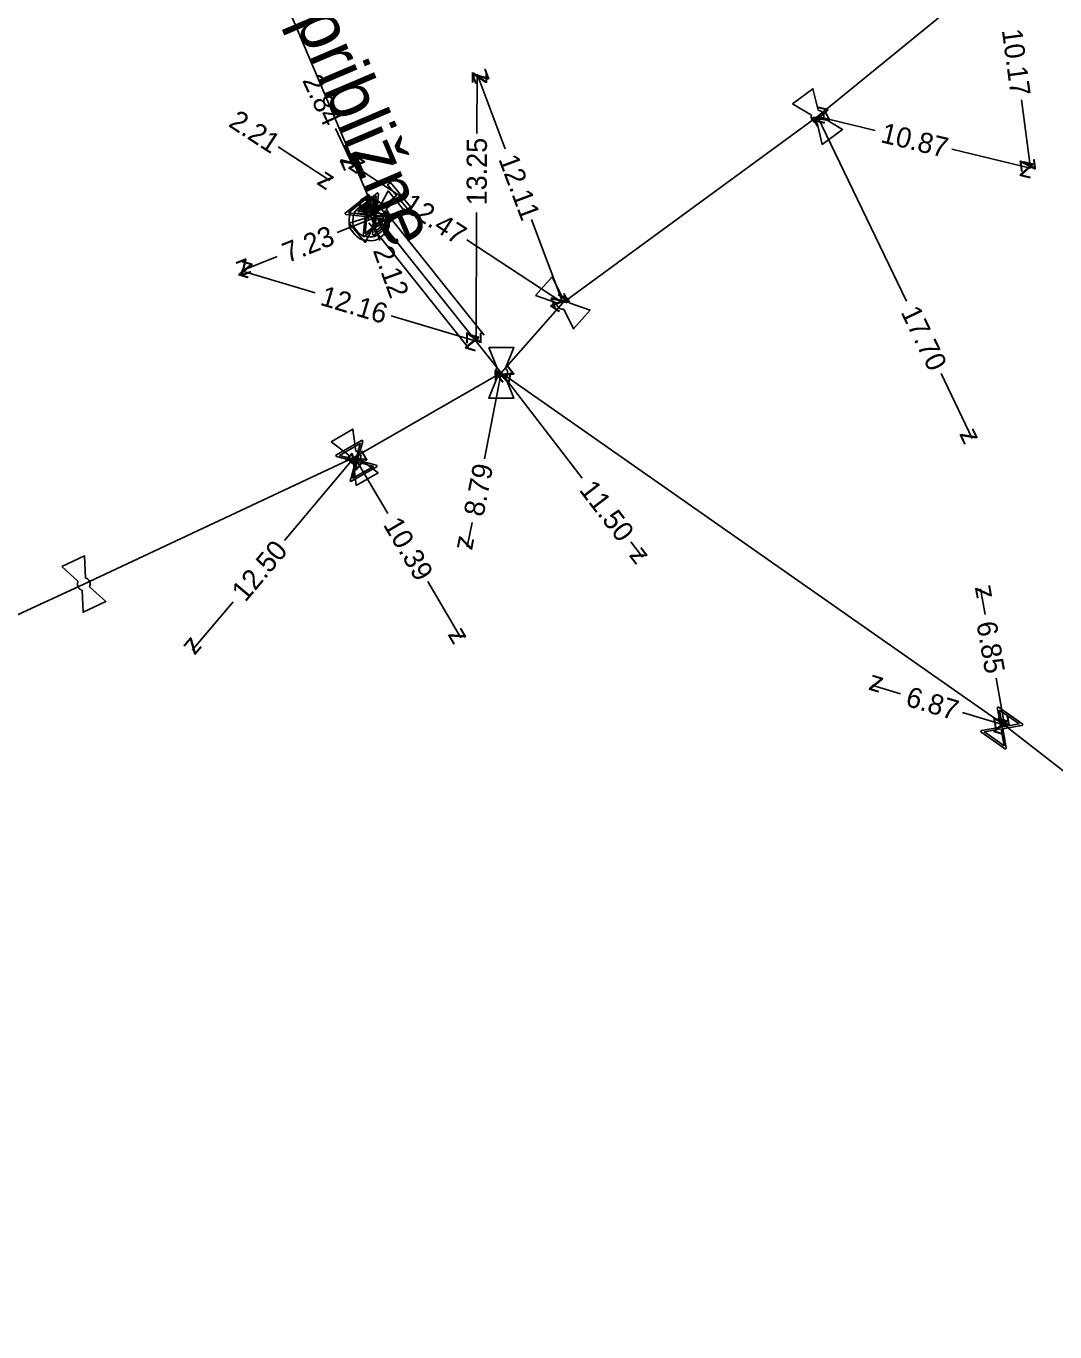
# Model space of a CAD drawing. Extents: x -638315 to -636370, y -1116147 to -1115110.
# Drawn here: x -637261.5 to -637210.5, y -1115972.2 to -1115907.4 of the extents above; entities that cross this region are included whole.
import ezdxf

# ---------------------------------------------------------------- set-up
doc = ezdxf.new("R2010")
doc.units = 0
for name, color, linetype in [('Default', 7, 'Continuous'), ('VP Chránička', 7, 'Continuous'), ('VP Hydrant', 7, 'Continuous'), ('VP Kótování', 7, 'Continuous'), ('VP Lomový bod', 7, 'Continuous'), ('VP Popis nerozlišený', 7, 'Continuous'), ('VP Přípojka', 7, 'Continuous'), ('VP Řad', 7, 'Continuous'), ('VP Šoupě', 7, 'Continuous')]:
    doc.layers.add(name, color=color, linetype=linetype)

msp = doc.modelspace()

# ---------------------------------------------------------------- linework, layer by layer
at = {"layer": 'Default'}
for points in [[(-637222.235, -1115911.617), (-637222.183, -1115911.622), (-637222.134, -1115911.643), (-637222.056, -1115911.68), (-637222.008, -1115911.746), (-637221.96, -1115911.812), (-637221.95, -1115911.896), (-637221.944, -1115911.95), (-637221.956, -1115912.001)], [(-637222.285, -1115912.242), (-637222.338, -1115912.238), (-637222.388, -1115912.215), (-637222.464, -1115912.181), (-637222.513, -1115912.115), (-637222.561, -1115912.049), (-637222.571, -1115911.962), (-637222.578, -1115911.91), (-637222.565, -1115911.858)], [(-637243.654, -1115916.505), (-637243.448, -1115916.801), (-637243.483, -1115917.165), (-637243.523, -1115917.576), (-637243.844, -1115917.841), (-637244.163, -1115918.105), (-637244.575, -1115918.066), (-637244.986, -1115918.026), (-637245.252, -1115917.706), (-637245.514, -1115917.388), (-637245.476, -1115916.976), (-637245.438, -1115916.564), (-637245.119, -1115916.3), (-637244.799, -1115916.035), (-637244.387, -1115916.073), (-637244.021, -1115916.104), (-637243.771, -1115916.364)], [(-637244.975, -1115916.31), (-637244.975, -1115916.216), (-637244.927, -1115916.126), (-637244.878, -1115916.036), (-637244.788, -1115915.986), (-637244.698, -1115915.935), (-637244.6, -1115915.935), (-637244.502, -1115915.935), (-637244.413, -1115915.984), (-637244.324, -1115916.034), (-637244.274, -1115916.123), (-637244.225, -1115916.213), (-637244.225, -1115916.31), (-637244.225, -1115916.407), (-637244.274, -1115916.497), (-637244.324, -1115916.586), (-637244.413, -1115916.636), (-637244.502, -1115916.685), (-637244.6, -1115916.685), (-637244.698, -1115916.685), (-637244.788, -1115916.635), (-637244.878, -1115916.584), (-637244.927, -1115916.495), (-637244.975, -1115916.405), (-637244.975, -1115916.31)], [(-637244.928, -1115916.31), (-637244.928, -1115916.393), (-637244.886, -1115916.472), (-637244.844, -1115916.55), (-637244.765, -1115916.594), (-637244.686, -1115916.638), (-637244.6, -1115916.638), (-637244.514, -1115916.638), (-637244.436, -1115916.595), (-637244.359, -1115916.552), (-637244.315, -1115916.474), (-637244.272, -1115916.395), (-637244.272, -1115916.31), (-637244.272, -1115916.225), (-637244.315, -1115916.146), (-637244.359, -1115916.068), (-637244.436, -1115916.025), (-637244.514, -1115915.982), (-637244.6, -1115915.982), (-637244.686, -1115915.982), (-637244.765, -1115916.026), (-637244.844, -1115916.071), (-637244.886, -1115916.149), (-637244.928, -1115916.228), (-637244.928, -1115916.31)], [(-637243.854, -1115916.549), (-637244.069, -1115916.289), (-637244.403, -1115916.257), (-637244.737, -1115916.225), (-637244.998, -1115916.441), (-637245.258, -1115916.656), (-637245.29, -1115916.99), (-637245.321, -1115917.325), (-637245.106, -1115917.585), (-637244.892, -1115917.844), (-637244.557, -1115917.876), (-637244.222, -1115917.908), (-637243.962, -1115917.693), (-637243.701, -1115917.477), (-637243.67, -1115917.143), (-637243.638, -1115916.809), (-637243.854, -1115916.549)], [(-637244.432, -1115916.884), (-637244.432, -1115916.831), (-637244.412, -1115916.78), (-637244.382, -1115916.701), (-637244.319, -1115916.649), (-637244.256, -1115916.597), (-637244.171, -1115916.582), (-637244.119, -1115916.572), (-637244.067, -1115916.581)], [(-637243.806, -1115916.896), (-637243.807, -1115916.948), (-637243.826, -1115916.998), (-637243.858, -1115917.079), (-637243.921, -1115917.131), (-637243.984, -1115917.183), (-637244.067, -1115917.198), (-637244.121, -1115917.207), (-637244.173, -1115917.198)], [(-637234.846, -1115921.469), (-637234.899, -1115921.477), (-637234.952, -1115921.466), (-637235.035, -1115921.449), (-637235.096, -1115921.395), (-637235.157, -1115921.341), (-637235.186, -1115921.259), (-637235.204, -1115921.209), (-637235.203, -1115921.156)], [(-637234.933, -1115920.849), (-637234.882, -1115920.842), (-637234.829, -1115920.852), (-637234.745, -1115920.871), (-637234.683, -1115920.925), (-637234.622, -1115920.979), (-637234.594, -1115921.059), (-637234.576, -1115921.11), (-637234.577, -1115921.163)], [(-637238.144, -1115924.867), (-637238.184, -1115924.833), (-637238.211, -1115924.785), (-637238.253, -1115924.712), (-637238.253, -1115924.63), (-637238.253, -1115924.548), (-637238.21, -1115924.473), (-637238.184, -1115924.426), (-637238.144, -1115924.392)], [(-637237.735, -1115924.392), (-637237.696, -1115924.426), (-637237.669, -1115924.473), (-637237.628, -1115924.548), (-637237.628, -1115924.63), (-637237.628, -1115924.712), (-637237.669, -1115924.785), (-637237.696, -1115924.833), (-637237.736, -1115924.867)], [(-637245.271, -1115929.12), (-637245.323, -1115929.111), (-637245.37, -1115929.083), (-637245.443, -1115929.04), (-637245.484, -1115928.969), (-637245.524, -1115928.898), (-637245.525, -1115928.811), (-637245.526, -1115928.758), (-637245.508, -1115928.709)], [(-637245.154, -1115928.505), (-637245.103, -1115928.515), (-637245.056, -1115928.542), (-637244.983, -1115928.587), (-637244.942, -1115928.657), (-637244.901, -1115928.728), (-637244.9, -1115928.813), (-637244.9, -1115928.867), (-637244.918, -1115928.917)], [(-637258.555, -1115934.797), (-637258.505, -1115934.812), (-637258.461, -1115934.842), (-637258.392, -1115934.893), (-637258.357, -1115934.967), (-637258.322, -1115935.041), (-637258.329, -1115935.125), (-637258.333, -1115935.18), (-637258.355, -1115935.228)], [(-637258.724, -1115935.401), (-637258.775, -1115935.387), (-637258.82, -1115935.355), (-637258.888, -1115935.306), (-637258.923, -1115935.232), (-637258.958, -1115935.158), (-637258.951, -1115935.072), (-637258.948, -1115935.019), (-637258.926, -1115934.971)]]:
    msp.add_open_spline(points, degree=3, dxfattribs=at)
at = {"layer": 'VP Chránička'}
for points in [[(-637243.729, -1115916.578), (-637238.797, -1115922.755)], [(-637244.51, -1115917.201), (-637239.578, -1115923.378)]]:
    msp.add_lwpolyline(points, dxfattribs=at)
at = {"layer": 'VP Hydrant'}
msp.add_lwpolyline([(-637243.771, -1115916.364), (-637243.139, -1115915.841), (-637243.579, -1115915.31), (-637243.437, -1115915.193), (-637242.441, -1115916.396), (-637242.583, -1115916.513), (-637243.022, -1115915.982), (-637243.654, -1115916.505)], dxfattribs=at)
at = {"layer": 'VP Kótování'}
for points in [[(-637239.151, -1115912.767), (-637239.14, -1115909.82)], [(-637237.75, -1115913.528), (-637239.14, -1115909.82)], [(-637212.158, -1115911.104), (-637211.7, -1115914.49)], [(-637219.406, -1115912.622), (-637222.26, -1115911.93)], [(-637217.859, -1115921.082), (-637222.26, -1115911.93)], [(-637246.165, -1115912.511), (-637245.32, -1115914.32)], [(-637249.004, -1115913.43), (-637246.45, -1115915.1)], [(-637245.677, -1115913.333), (-637245.32, -1115914.32)], [(-637215.607, -1115913.543), (-637211.7, -1115914.49)], [(-637242.924, -1115915.891), (-637245.32, -1115914.32)], [(-637243.966, -1115918.063), (-637244.6, -1115916.31)], [(-637243.721, -1115916.885), (-637244.6, -1115916.31)], [(-637239.165, -1115916.677), (-637239.188, -1115923.067)], [(-637246.072, -1115917.67), (-637244.12, -1115916.89)], [(-637243.676, -1115917.841), (-637244.12, -1115916.89)], [(-637236.44, -1115917.024), (-637234.89, -1115921.16)], [(-637239.656, -1115918.034), (-637234.89, -1115921.16)], [(-637249.052, -1115918.86), (-637250.83, -1115919.57)], [(-637247.17, -1115920.67), (-637250.83, -1115919.57)], [(-637243.395, -1115921.803), (-637239.188, -1115923.067)], [(-637238.776, -1115928.897), (-637237.94, -1115924.63)], [(-637233.934, -1115929.856), (-637237.94, -1115924.63)], [(-637216.141, -1115924.654), (-637214.59, -1115927.88)], [(-637248.687, -1115932.943), (-637245.213, -1115928.813)], [(-637243.57, -1115931.601), (-637245.213, -1115928.813)], [(-637239.392, -1115932.046), (-637239.63, -1115933.26)], [(-637231.522, -1115933.001), (-637230.94, -1115933.76)], [(-637241.586, -1115934.968), (-637239.94, -1115937.76)], [(-637213.958, -1115936.602), (-637214.18, -1115935.34)], [(-637251.238, -1115935.976), (-637253.26, -1115938.38)], [(-637218.143, -1115940.53), (-637219.57, -1115940.1)], [(-637213.401, -1115939.764), (-637212.993, -1115942.084)], [(-637215.072, -1115941.457), (-637212.993, -1115942.084)]]:
    msp.add_lwpolyline(points, dxfattribs=at)
at = {"layer": 'VP Lomový bod'}
for points in [[(-637223.502, -1115911.29), (-637222.493, -1115910.552), (-637222.235, -1115911.617)], [(-637222.565, -1115911.858), (-637223.502, -1115911.29)], [(-637221.956, -1115912.001), (-637221.018, -1115912.571), (-637222.027, -1115913.308), (-637222.285, -1115912.242)], [(-637244.067, -1115916.581), (-637243.556, -1115915.612)], [(-637243.556, -1115915.612), (-637242.759, -1115916.575), (-637243.806, -1115916.896)], [(-637244.173, -1115917.198), (-637244.685, -1115918.168), (-637245.482, -1115917.205), (-637244.432, -1115916.884)], [(-637236.241, -1115920.804), (-637235.416, -1115919.865), (-637234.933, -1115920.849)], [(-637235.203, -1115921.156), (-637236.241, -1115920.804)], [(-637234.577, -1115921.163), (-637233.538, -1115921.516), (-637234.363, -1115922.455), (-637234.846, -1115921.469)], [(-637238.565, -1115923.38), (-637237.315, -1115923.38), (-637237.735, -1115924.392)], [(-637238.144, -1115924.392), (-637238.565, -1115923.38)], [(-637237.736, -1115924.867), (-637237.315, -1115925.88), (-637238.565, -1115925.88), (-637238.144, -1115924.867)], [(-637246.378, -1115928.041), (-637245.294, -1115927.418), (-637245.154, -1115928.505)], [(-637245.508, -1115928.709), (-637246.378, -1115928.041)], [(-637244.918, -1115928.917), (-637244.048, -1115929.585), (-637245.131, -1115930.208), (-637245.271, -1115929.12)], [(-637259.736, -1115934.233), (-637258.604, -1115933.703), (-637258.555, -1115934.797)], [(-637258.926, -1115934.971), (-637259.736, -1115934.233)], [(-637258.355, -1115935.228), (-637257.544, -1115935.967), (-637258.676, -1115936.497), (-637258.724, -1115935.401)]]:
    msp.add_lwpolyline(points, dxfattribs=at)
at = {"layer": 'VP Přípojka'}
for points in [[(-637244.12, -1115916.89), (-637258.991, -1115881.881)], [(-637244.507, -1115917.006), (-637244.695, -1115916.772), (-637244.883, -1115916.538)], [(-637245.213, -1115928.813), (-637245.12, -1115928.99)], [(-637213.13, -1115942.23), (-637212.993, -1115942.084)]]:
    msp.add_lwpolyline(points, dxfattribs=at)
at = {"layer": 'VP Řad'}
for points in [[(-637237.94, -1115924.63), (-637234.89, -1115921.16), (-637222.26, -1115911.93), (-637213.062, -1115904.409), (-637210.258, -1115901.954), (-637204.83, -1115897.2), (-637199.8, -1115891.84), (-637193.2, -1115884.012), (-637190.02, -1115880.24), (-637188.874, -1115878.812), (-637184.355, -1115873.178), (-637181.977, -1115870.214), (-637180.72, -1115868.647), (-637176.92, -1115863.91)], [(-637244.6, -1115916.31), (-637244.12, -1115916.89), (-637237.94, -1115924.63)], [(-637237.94, -1115924.63), (-637245.213, -1115928.813), (-637258.64, -1115935.1), (-637264.53, -1115937.81), (-637268.28, -1115940.82), (-637282.713, -1115953.66), (-637288.782, -1115958.83), (-637300.546, -1115968.853), (-637302.282, -1115970.332)], [(-637237.94, -1115924.63), (-637212.993, -1115942.084), (-637200.588, -1115951.742), (-637198.29, -1115953.52), (-637189.11, -1115959.05), (-637187.26, -1115960.04), (-637174.427, -1115967.22), (-637166.44, -1115972.16)]]:
    msp.add_lwpolyline(points, dxfattribs=at)
at = {"layer": 'VP Šoupě'}
for points in [[(-637243.586, -1115916.953), (-637244.755, -1115917.894), (-637244.796, -1115917.842), (-637244.778, -1115917.715), (-637244.689, -1115916.88), (-637245.654, -1115916.776), (-637245.695, -1115916.725), (-637244.526, -1115915.785), (-637244.485, -1115915.836), (-637244.592, -1115916.802), (-637243.756, -1115916.891), (-637243.627, -1115916.902), (-637243.586, -1115916.953)], [(-637245.518, -1115916.703), (-637244.679, -1115916.792), (-637244.59, -1115915.956), (-637245.518, -1115916.703)], [(-637243.123, -1115916.859), (-637244.279, -1115917.816), (-637244.321, -1115917.765), (-637244.304, -1115917.637), (-637244.227, -1115916.801), (-637245.193, -1115916.711), (-637245.235, -1115916.66), (-637244.079, -1115915.704), (-637244.037, -1115915.754), (-637244.131, -1115916.722), (-637243.294, -1115916.799), (-637243.165, -1115916.808), (-637243.123, -1115916.859)], [(-637245.058, -1115916.635), (-637244.218, -1115916.713), (-637244.14, -1115915.876), (-637245.058, -1115916.635)], [(-637243.304, -1115916.887), (-637244.139, -1115916.809), (-637244.217, -1115917.643), (-637243.304, -1115916.887)], [(-637243.767, -1115916.979), (-637244.601, -1115916.889), (-637244.69, -1115917.722), (-637243.767, -1115916.979)], [(-637244.096, -1115929.266), (-637245.396, -1115930.014), (-637245.429, -1115929.957), (-637245.392, -1115929.834), (-637245.174, -1115929.023), (-637246.111, -1115928.771), (-637246.144, -1115928.714), (-637244.844, -1115927.966), (-637244.811, -1115928.023), (-637245.066, -1115928.961), (-637244.255, -1115929.179), (-637244.129, -1115929.209), (-637244.096, -1115929.266)], [(-637245.965, -1115928.719), (-637245.151, -1115928.938), (-637244.933, -1115928.126), (-637245.965, -1115928.719)], [(-637244.279, -1115929.264), (-637245.089, -1115929.046), (-637245.306, -1115929.854), (-637244.279, -1115929.264)], [(-637213.314, -1115941.185), (-637212.085, -1115942.045), (-637212.123, -1115942.099), (-637212.25, -1115942.117), (-637213.077, -1115942.264), (-637212.907, -1115943.22), (-637212.945, -1115943.274), (-637214.174, -1115942.414), (-637214.136, -1115942.36), (-637213.179, -1115942.193), (-637213.326, -1115941.366), (-637213.352, -1115941.239), (-637213.314, -1115941.185)], [(-637213.239, -1115941.352), (-637213.092, -1115942.178), (-637212.268, -1115942.031), (-637213.239, -1115941.352)], [(-637213.016, -1115943.11), (-637213.164, -1115942.28), (-637213.992, -1115942.427), (-637213.016, -1115943.11)]]:
    msp.add_lwpolyline(points, dxfattribs=at)

# ---------------------------------------------------------------- texts
at = {"layer": 'VP Kótování'}
for s, rotation, p in [('10.17', 277.69437, (-637213.129, -1115907.644)), ('z', 110.54499, (-637238.496, -1115910.113)), ('2.84', 295.02909, (-637247.827, -1115910.132)), ('z', 89.7924, (-637238.642, -1115910.322)), ('z', 115.68184, (-637221.593, -1115912.164)), ('z', 166.37302, (-637221.656, -1115911.562)), ('2.21', 326.81312, (-637251.523, -1115912.379)), ('10.87', 346.37298, (-637219.183, -1115913.19)), ('13.25', 89.7924, (-637238.664, -1115916.329)), ('z', 295.02911, (-637245.985, -1115914.078)), ('z', 289.89059, (-637245.96, -1115914.02)), ('z', 146.74314, (-637244.628, -1115914.176)), ('12.11', 290.54495, (-637238.096, -1115914.031)), ('z', 277.69438, (-637212.262, -1115914.061)), ('z', 346.373, (-637212.304, -1115914.858)), ('z', 326.81314, (-637247.142, -1115915.245)), ('z', 109.89055, (-637243.96, -1115916.61)), ('z', 146.81316, (-637243.908, -1115916.165)), ('12.47', 326.74311, (-637242.906, -1115916.501)), ('z', 21.77194, (-637244.399, -1115917.54)), ('z', 115.02907, (-637243.455, -1115917.132)), ('7.23', 21.77194, (-637248.541, -1115919.194)), ('2.12', 289.89057, (-637244.317, -1115918.562)), ('z', 201.77198, (-637250.551, -1115918.92)), ('z', 163.28088, (-637250.207, -1115919.235)), ('12.16', 343.2809, (-637246.978, -1115921.249)), ('z', 290.54497, (-637235.534, -1115920.867)), ('z', 326.74312, (-637235.582, -1115921.304)), ('17.70', 295.68186, (-637218.158, -1115921.614)), ('z', 269.79238, (-637239.686, -1115922.565)), ('z', 343.28092, (-637239.811, -1115923.402)), ('z', 78.92007, (-637237.545, -1115925.217)), ('z', 127.47749, (-637237.239, -1115924.723)), ('z', 295.68188, (-637215.257, -1115927.646)), ('z', 49.93213, (-637245.152, -1115929.517)), ('z', 120.51336, (-637244.528, -1115928.99)), ('8.79', 78.92007, (-637238.834, -1115931.798)), ('11.50', 307.47751, (-637234.117, -1115930.438)), ('10.39', 300.51338, (-637243.823, -1115932.156)), ('12.50', 49.93213, (-637250.63, -1115936.03)), ('z', 258.92005, (-637240.025, -1115932.673)), ('z', 307.47747, (-637231.641, -1115933.667)), ('z', 99.98228, (-637213.601, -1115935.746)), ('z', 300.5134, (-637240.625, -1115937.583)), ('6.85', 279.9823, (-637214.39, -1115937.033)), ('z', 229.93211, (-637253.321, -1115937.676)), ('z', 163.21367, (-637218.947, -1115939.766)), ('6.87', 343.21369, (-637217.953, -1115941.11)), ('z', 343.21365, (-637213.616, -1115942.418)), ('z', 279.98232, (-637213.572, -1115941.678))]:
    msp.add_text(s, height=1, rotation=rotation, dxfattribs=at).set_placement(p)
at = {"layer": 'VP Popis nerozlišený'}
msp.add_text('zakresleno približne', height=2.5, rotation=293.01463, dxfattribs=at).set_placement((-637254.895, -1115891.398))

doc.saveas('drawing.dxf')
